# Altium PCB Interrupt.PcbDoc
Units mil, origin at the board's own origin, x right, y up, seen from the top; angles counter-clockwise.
Board outline 6000 x 4000 mil, 2 copper layers (Top Layer, Bottom Layer); 13 components, 13 nets, 46 pads, 0 vias.
Unrouted connection lines stored in the file: 28.
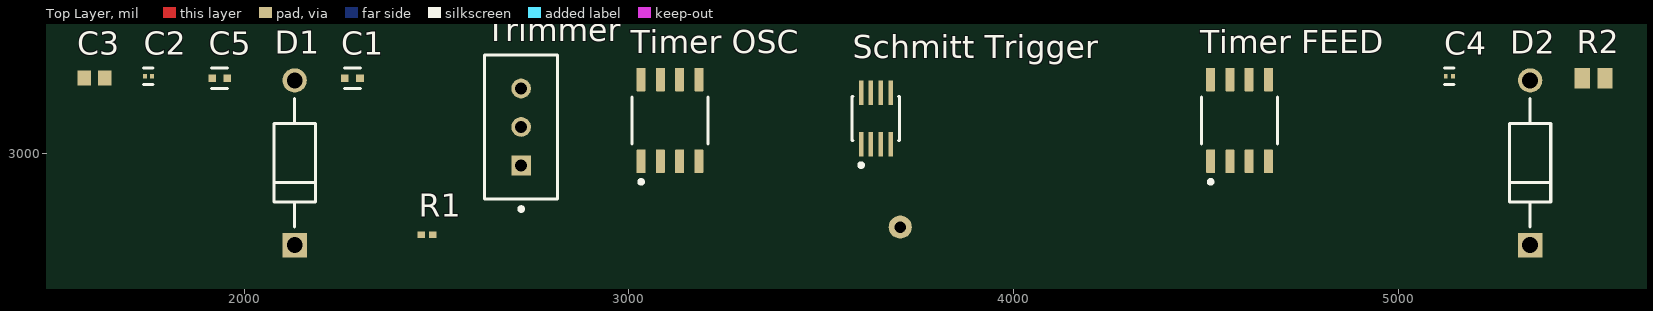
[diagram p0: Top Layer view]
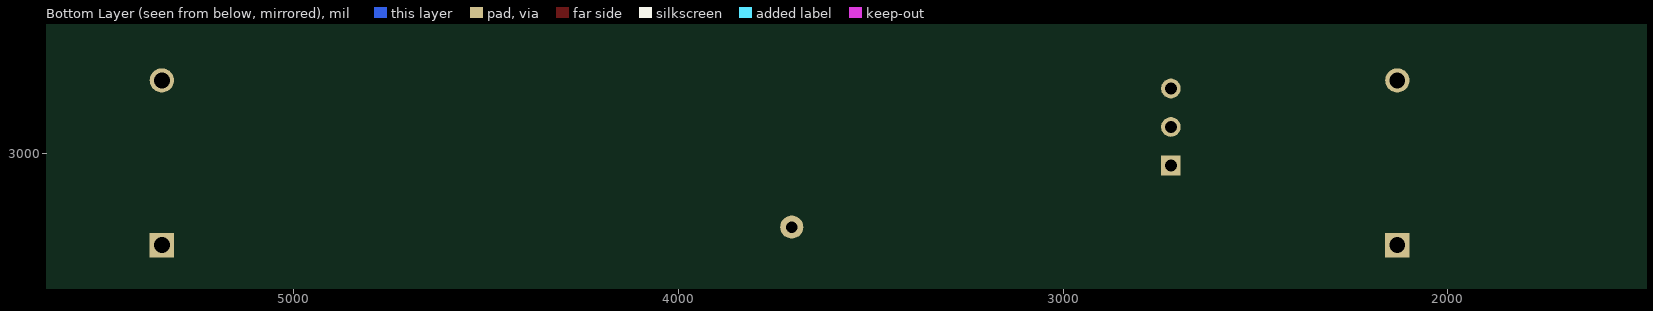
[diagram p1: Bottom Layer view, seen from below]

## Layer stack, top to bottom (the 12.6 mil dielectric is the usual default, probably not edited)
Top Solder: solder mask 0.4, Solder Resist, Dk 3.5
Top Layer: signal copper 1.4
Dielectric 1: dielectric 12.6, FR-4, Dk 4.8
Bottom Layer: signal copper 1.4
Bottom Solder: solder mask 0.4, Solder Resist, Dk 3.5

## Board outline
1000,1000 7000,1000 7000,5000 1000,5000

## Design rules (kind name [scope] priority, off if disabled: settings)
Clearance [All] p1: gap=10 ignorepadtopadclearanceinfootprint=FALSE except(0: Arc-Hole Track-Hole SMDPad-Hole THPad-Hole Via-Hole Fill-Hole Poly-Hole Region-Hole Text-Hole)
PolygonConnect [All] p1: connectstyle=Relief reliefconductorwidth=10 reliefentries=4 polygonreliefangle="90 Angle" airgapwidth=10
RoomDefinition Interrupt [InComponentClass('Interrupt')] p1: confinementstyle=ConfineIn formatcopy=TRUE lockcomponents=FALSE outline 1551.61,2716.93 5581.61,2716.93 5581.61,3336.93 1551.61,3336.93
RoutingVias [All] p1: holewidth=28 width=50 viastyle="Through Hole" minholewidth=28 minwidth=50 maxholewidth=28 maxwidth=50
SolderMaskExpansion [All] p1: expansion=4 istentingtop=FALSE
Width [All] p1: maxlimit=10 minlimit=10 preferedwidth=10
30 further rules are at their usual default settings.

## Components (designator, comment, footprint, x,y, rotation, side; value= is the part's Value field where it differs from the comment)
C1 "CC0402MRX5R5BB224" FP-CC0402-MFG 2281.61,3196.93 r0 top value="220 nF"
C2 "GRM033R60J104KE19D" FP-GRM033-0_03-MFG 1751.61,3201.93 r0 top
C3 "C0603S222K5RACTU" CAPC1608X87X35NL15T15 1611.61,3196.93 r0 top
C4 "GRM033R60J104KE19D" FP-GRM033-0_03-MFG 5131.61,3201.93 r0 top
C5 "CC0402MRX5R5BB224" FP-CC0402-MFG 1936.61,3196.93 r0 top value="220 nF"
D1 "UF4007" FP-017AH-MFG 2131.61,2976.93 r90 top value=17pF
D2 "UF4007" FP-017AH-MFG 5341.61,2976.93 r90 top value=17pF
R1 "RC0402FR-0710KL" RESC1005X40X25LL05T10 2475,2790 r0 top
R2 "ERA6AEB473V" RESC2013X60X40LL20T25 5506.61,3196.93 r0 top
"Schmitt Trigger" "SN74LVC3G17DCTR" FP-DCT0008A-MFG 3641.61,3091.93 r90 top
"Timer FEED" "LMC555CMX/NOPB" FP-D0008A-MFG 4586.61,3086.93 r90 top
"Timer OSC" "LMC555CMX/NOPB" FP-D0008A-MFG 3106.61,3086.93 r90 top
Trimmer "3296W-1-103LF" BOUR-3296W 2720,3070 r90 top

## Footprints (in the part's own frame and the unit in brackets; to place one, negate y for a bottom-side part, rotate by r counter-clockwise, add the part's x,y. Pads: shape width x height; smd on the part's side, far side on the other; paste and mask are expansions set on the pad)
BOUR-3296W [mm] "THD, 3-Leads, Body 9.53x4.83mm, Pitch 2.54mm"
  rect 1.3x1.3 hole 0.8: 1(-2.54,0)
  round 1.3 hole 0.8: 2(0,0) 3(2.54,0)
  silkscreen extent -5.54,-2.41 4.76,2.42, body extent -4.76,-2.4 4.76,2.42, height 11.55
CAPC1608X87X35NL15T15 [mm] "Chip Capacitor, 2-Leads, Body 1.60x0.80mm, IPC Medium Density"
  rect 0.9x1 smd: 1(-0.675,0) 2(0.675,0)
  body extent -0.87,-0.48 0.87,0.47, height 0.87
FP-017AH-MFG [mm]
  rect 1.6x1.6 hole 1.05 paste-1000 mask+0: 1(-5.438,0)
  round 1.6 hole 1.05 paste-1000 mask+0: 2(5.438,0)
  silkscreen extent -4.24,-1.36 4.24,1.36, body extent -6.34,-1.46 6.34,1.46, height 0.25
FP-CC0402-MFG [mm]
  rect 0.5x0.5 smd paste+0 mask+0: 1(-0.5,0) 2(0.5,0)
  silkscreen extent -0.53,-0.68 0.53,0.67, body extent -0.87,-0.48 0.87,0.48, height 0.25
FP-D0008A-MFG [mm]
  rrect17% 1.55x0.6 smd paste+0 mask+0: 1(-2.7,1.905) 2(-2.7,0.635) 3(-2.7,-0.635) 4(-2.7,-1.905) 5(2.7,-1.905) 6(2.7,-0.635) 7(2.7,0.635) 8(2.7,1.905)
  silkscreen extent -4.17,-2.5 1.55,2.5, body extent -3.57,-2.75 3.57,2.75, height 0.25
FP-DCT0008A-MFG [mm]
  rect 1.6x0.3 smd paste-1000 mask+0: 1(-1.7,0.975) 2(-1.7,0.325) 3(-1.7,-0.325) 4(-1.7,-0.975) 5(1.7,-0.975) 6(1.7,-0.325) 7(1.7,0.325) 8(1.7,0.975)
  silkscreen extent -3.2,-1.58 1.45,1.58, body extent -2.6,-1.68 2.6,1.68, height 0.25
FP-GRM033-0_03-MFG [mm]
  rect 0.25x0.3 smd paste+0 mask+0: 1(-0.238,0) 2(0.238,0)
  silkscreen extent -0.32,-0.54 0.32,0.54, body extent -0.46,-0.27 0.46,0.27, height 0.25
RESC1005X40X25LL05T10 [mm] "Chip Resistor, 2-Leads, Body 1.00x0.50mm, IPC High Density"
  rect 0.5x0.45 smd: 1(-0.375,0) 2(0.375,0)
  body extent -0.53,-0.27 0.53,0.28, height 0.4
RESC2013X60X40LL20T25 [mm] "Chip Resistor, 2-Leads, Body 2.00x1.25mm, IPC High Density"
  rect 1x1.35 smd: 1(-0.75,0) 2(0.75,0)
  body extent -1.1,-0.72 1.1,0.72, height 0.6

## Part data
C1 C5: library part CMP-03422-000657-1, "CAP CER 0.22UF 6.3V X5R 0402", Capacitance="220 nF", Manufacturer=YAGEO, Package=CC0402, Temperature="-55°C to +125°C", Temperature Characteristic=X5R, Temperature Coefficient=30ppm/°C, Temperature Range High=+125°C, Temperature Range Low=-55°C, Tolerance=0.2, Voltage Rating="6.3 V"
C2: library part CMP-06035-000062-2, "100 nF Chip Multilayer Ceramic Capacitors for General Purpose, 0201, 0.10uF, X5R, 15%, 10%, 6.3V", Capacitance=100nF, Case Code (Imperial)=0201, Case Code (Metric)=0603, Dielectric=X5R, Max Operating Temperature=85°C, Min Operating Temperature=-55°C, Package Quantity=1, Tolerance=10%, Voltage=6.3V
C3: library part CMP-2006-03289-1, Manufacturer=Kemet
C4: library part CMP-06035-000062-2, "Chip Multilayer Ceramic Capacitors for General Purpose, 0201, 0.10uF, X5R, 15%, 10%, 6.3V", Capacitance=100nF, Case Code (Imperial)=0201, Case Code (Metric)=0603, Dielectric=X5R, Max Operating Temperature=85°C, Min Operating Temperature=-55°C, Package Quantity=1, Tolerance=10%, Voltage=6.3V
D1 D2: library part CMP-2000-05028-2, "DIODE GEN PURP 1KV 1A DO41", Capacitance=17pF, Forward Current=1A, Manufacturer="ON Semiconductor", Max Junction Temp=+150°C, Max Repetitive Reverse Voltage=1000V, Max Surge Forward Current=30A, Package=017AH, Peak Reverse Current=10uA, Temperature="-65°C to +150°C", Temperature Range Low=-65°C
R1: library part CMP-2002-07353-1, "10Kohm", Manufacturer="Yageo / Phycomp"
R2: library part CMP-2001-00645-1, Manufacturer=Panasonic
"Schmitt Trigger": library part CMP-0859-00525-5, "IC BUFFER NON-INVERT 5.5V SM8", Ambient Temperature Range High=+125°C, Ambient Temperature Range Low=-40°C, Manufacturer="Texas Instruments", Max Supply Voltage=5.5V, Min Supply Voltage=1.65V, Nominal Supply Current=10uA, Package=DCT0008A, Temperature="-40°C to +125°C"
"Timer FEED" "Timer OSC": library part CMP-04858-000001-1, "IC OSC SINGLE TIMER 3MHZ 8-SOIC", Frequency=3MHz, Manufacturer="Texas Instruments", Max Supply Voltage=15V, Min Supply Voltage=1.5V, Nominal Supply Current=50-150uA, Package=D0008A, Temperature="-40°C to +85°C", Temperature Range High=+85°C, Temperature Range Low=-40°C
Trimmer: library part CMP-1747-00001-1, "Square Trimpot(R) Trimming Potentiometer, 10 KOhm, +/- 10%, 0.5 W, -55 to 125 degC, 3-Pin THD, RoHS, Tube", Case Code (Imperial)=0603, Case Code (Metric)=1608, Max Operating Temperature="155 degC", Min Operating Temperature="-55 degC", Package Quantity=5000, Power Rating="100 mW", Resistance="120 Ohm", Tolerance=1%, Type (Resistor)="Thick Film", Voltage Rating="75 V"

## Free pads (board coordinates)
  round 60 hole 30: 2(3705,2810)

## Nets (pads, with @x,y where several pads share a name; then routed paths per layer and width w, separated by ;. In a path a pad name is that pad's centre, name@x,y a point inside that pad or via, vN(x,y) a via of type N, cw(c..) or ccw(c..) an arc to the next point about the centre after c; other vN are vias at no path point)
GND: "Schmitt Trigger.6" "Timer FEED.1" "Timer FEED.7" "Timer OSC.1" C1.2 C2.2 C3.1 C5.2 D1.2
NetC2_1: "Timer OSC.5" C2.1
NetC3_2: "Timer OSC.2" "Timer OSC.6" C3.2 Trimmer.1
NetC4_1: C4.1
NetC4_2: "Schmitt Trigger.7" C4.2 D1.1 D2.2 R1.1
NetC5_1: "Timer FEED.3" "Timer FEED.8" C5.1 R2.2
NetR1_2: "Timer FEED.2" R1.2 R2.1
"NetSchmitt Trigger_1": "Schmitt Trigger.1" "Timer OSC.3" Trimmer.2
"NetSchmitt Trigger_2": "Schmitt Trigger.2"
"NetSchmitt Trigger_3": "Schmitt Trigger.3"
"NetSchmitt Trigger_4": "Schmitt Trigger.4" "Schmitt Trigger.5"
NetTrimmer_3: Trimmer.3
VCC: "Schmitt Trigger.8" "Timer FEED.4" "Timer OSC.8" C1.1 D2.1
pads on no net: "Timer FEED.5" "Timer FEED.6" "Timer OSC.4" "Timer OSC.7"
